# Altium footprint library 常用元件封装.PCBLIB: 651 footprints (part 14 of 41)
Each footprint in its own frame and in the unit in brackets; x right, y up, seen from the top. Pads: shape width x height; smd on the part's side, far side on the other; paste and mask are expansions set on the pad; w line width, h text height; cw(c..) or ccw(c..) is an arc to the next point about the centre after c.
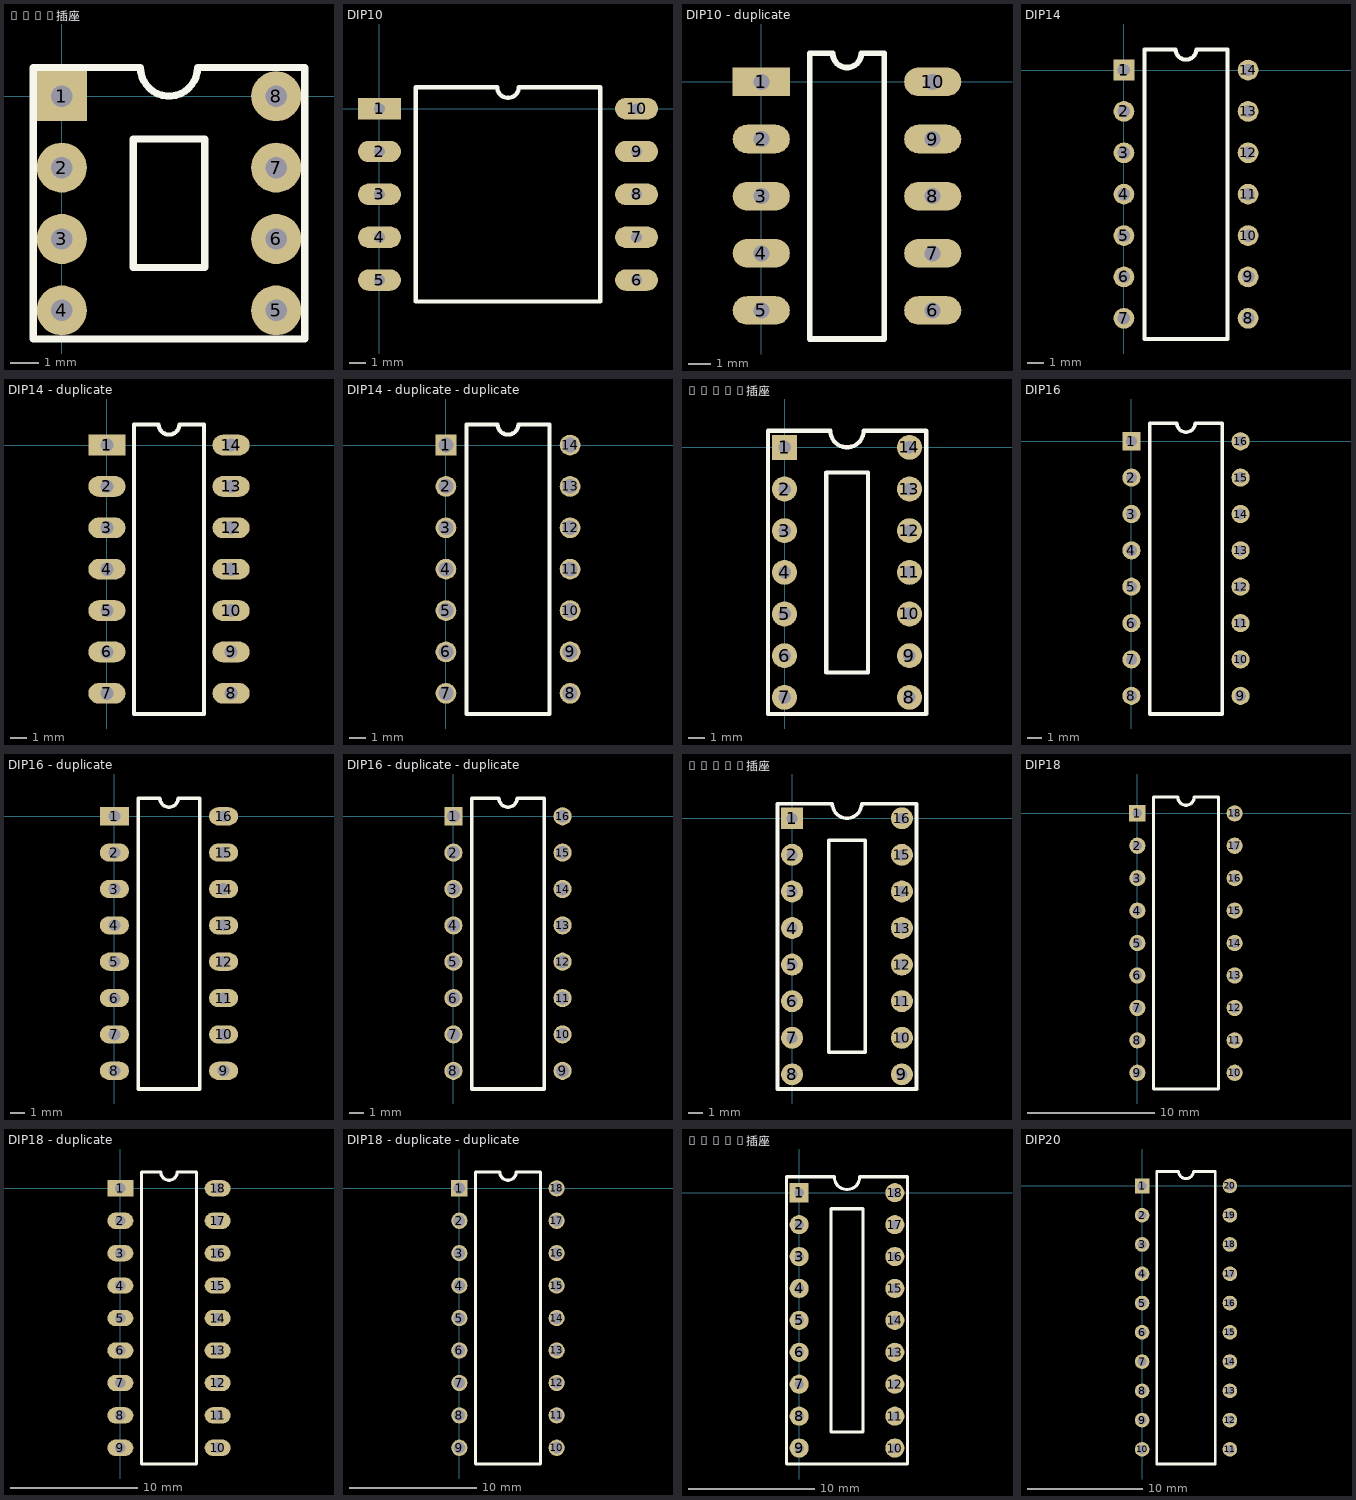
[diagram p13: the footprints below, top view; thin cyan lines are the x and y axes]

## DIP8插座 [mil]
pads (8):
  rect 70x70 hole 30: 1(0,0)
  round 70 hole 30: 2(0,-100) 3(0,-200) 4(0,-300) 5(300,-300) 6(300,-200) 7(300,-100) 8(300,0)
TopOverlay:
  lines w10: -40,-340 340,-340 340,40 190,40 cw(c150,40) 110,40 -40,40 -40,-340 ; 100,-240 100,-60 200,-60 200,-240 100,-240

## DIP10 [mil]
pads (10):
  rect 100x50 hole 25: 1(0,0)
  oval 100x50 hole 25: 2(0,-100) 3(0,-200) 4(0,-300) 5(0,-400) 6(600,-400) 7(600,-300) 8(600,-200) 9(600,-100) 10(600,0)
TopOverlay:
  lines w10: 85,-450 85,50 275,50 ccw(c300,50) 325,50 515,50 515,-450 85,-450

## DIP10 - duplicate [mil]
pads (10):
  rect 100x50 hole 28: 1(0,0)
  oval 100x50 hole 28: 2(0,-100) 3(0,-200) 4(0,-300) 5(0,-400) 6(300,-400) 7(300,-300) 8(300,-200) 9(300,-100) 10(300,0)
TopOverlay:
  lines w10: 85,-450 215,-450 215,50 175,50 cw(c150,50) 125,50 85,50 85,-450

## DIP14 [mil]
pads (14):
  rect 50x50 hole 30: 1(0,0)
  round 50 hole 30: 2(0,-100) 3(0,-200) 4(0,-300) 5(0,-400) 6(0,-500) 7(0,-600) 8(300,-600) 9(300,-500) 10(300,-400) 11(300,-300) 12(300,-200) 13(300,-100) 14(300,0)
TopOverlay:
  lines w10: 50,-650 50,50 125,50 ccw(c150,50) 175,50 250,50 250,-650 50,-650

## DIP14 - duplicate [mil]
pads (14):
  rect 90x50 hole 32: 1(0,0)
  oval 90x50 hole 32: 2(0,-100) 3(0,-200) 4(0,-300) 5(0,-400) 6(0,-500) 7(0,-600) 8(300,-600) 9(300,-500) 10(300,-400) 11(300,-300) 12(300,-200) 13(300,-100) 14(300,0)
TopOverlay:
  lines w10: 65,-650 65,50 125,50 ccw(c150,50) 175,50 235,50 235,-650 65,-650

## DIP14 - duplicate - duplicate [mm]
pads (14):
  rect 1.27x1.27 hole 0.9: 1(0,0)
  round 1.27 hole 0.9: 2(0,-2.54) 3(0,-5.08) 4(0,-7.62) 5(0,-10.16) 6(0,-12.7) 7(0,-15.24) 8(7.62,-15.24) 9(7.62,-12.7) 10(7.62,-10.16) 11(7.62,-7.62) 12(7.62,-5.08) 13(7.62,-2.54) 14(7.62,0)
TopOverlay:
  lines w0.254: 1.27,-16.51 6.35,-16.51 6.35,1.27 4.445,1.27 cw(c3.81,1.27) 3.175,1.27 1.27,1.27 1.27,-16.51

## DIP14插座 [mil]
pads (14):
  rect 60x60 hole 30: 1(0,0)
  round 60 hole 30: 2(0,-100) 3(0,-200) 4(0,-300) 5(0,-400) 6(0,-500) 7(0,-600) 8(300,-600) 9(300,-500) 10(300,-400) 11(300,-300) 12(300,-200) 13(300,-100) 14(300,0)
TopOverlay:
  lines w10: -40,-640 340,-640 340,40 190,40 cw(c150,40) 110,40 -40,40 -40,-640 ; 100,-540 100,-60 200,-60 200,-540 100,-540

## DIP16 [mil]
pads (16):
  rect 50x50 hole 30: 1(0,0)
  round 50 hole 30: 2(0,-100) 3(0,-200) 4(0,-300) 5(0,-400) 6(0,-500) 7(0,-600) 8(0,-700) 9(300,-700) 10(300,-600) 11(300,-500) 12(300,-400) 13(300,-300) 14(300,-200) 15(300,-100) 16(300,0)
TopOverlay:
  lines w10: 50,-750 250,-750 250,50 175,50 cw(c150,50) 125,50 50,50 50,-750

## DIP16 - duplicate [mil]
pads (16):
  rect 80x50 hole 32: 1(0,0)
  oval 80x50 hole 32: 2(0,-100) 3(0,-200) 4(0,-300) 5(0,-400) 6(0,-500) 7(0,-600) 8(0,-700) 9(300,-700) 10(300,-600) 11(300,-500) 12(300,-400) 13(300,-300) 14(300,-200) 15(300,-100) 16(300,0)
TopOverlay:
  lines w10: 65,-750 65,50 125,50 ccw(c150,50) 175,50 235,50 235,-750 65,-750

## DIP16 - duplicate - duplicate [mm]
pads (16):
  rect 1.27x1.27 hole 0.9: 1(0,0)
  round 1.27 hole 0.9: 2(0,-2.54) 3(0,-5.08) 4(0,-7.62) 5(0,-10.16) 6(0,-12.7) 7(0,-15.24) 8(0,-17.78) 9(7.62,-17.78) 10(7.62,-15.24) 11(7.62,-12.7) 12(7.62,-10.16) 13(7.62,-7.62) 14(7.62,-5.08) 15(7.62,-2.54) 16(7.62,0)
TopOverlay:
  lines w0.254: 1.27,-19.05 6.35,-19.05 6.35,1.27 4.445,1.27 cw(c3.81,1.27) 3.175,1.27 1.27,1.27 1.27,-19.05

## DIP16插座 [mil]
pads (16):
  rect 60x60 hole 30: 1(0,0)
  round 60 hole 30: 2(0,-100) 3(0,-200) 4(0,-300) 5(0,-400) 6(0,-500) 7(0,-600) 8(0,-700) 9(300,-700) 10(300,-600) 11(300,-500) 12(300,-400) 13(300,-300) 14(300,-200) 15(300,-100) 16(300,0)
TopOverlay:
  lines w10: -40,-740 340,-740 340,40 190,40 cw(c150,40) 110,40 -40,40 -40,-740 ; 100,-640 100,-60 200,-60 200,-640 100,-640

## DIP18 [mil]
pads (18):
  rect 50x50 hole 30: 1(0,0)
  round 50 hole 30: 2(0,-100) 3(0,-200) 4(0,-300) 5(0,-400) 6(0,-500) 7(0,-600) 8(0,-700) 9(0,-800) 10(300,-800) 11(300,-700) 12(300,-600) 13(300,-500) 14(300,-400) 15(300,-300) 16(300,-200) 17(300,-100) 18(300,0)
TopOverlay:
  lines w10: 50,-850 250,-850 250,50 175,50 cw(c150,50) 125,50 50,50 50,-850

## DIP18 - duplicate [mil]
pads (18):
  rect 80x50 hole 32: 1(0,0)
  oval 80x50 hole 32: 2(0,-100) 3(0,-200) 4(0,-300) 5(0,-400) 6(0,-500) 7(0,-600) 8(0,-700) 9(0,-800) 10(300,-800) 11(300,-700) 12(300,-600) 13(300,-500) 14(300,-400) 15(300,-300) 16(300,-200) 17(300,-100) 18(300,0)
TopOverlay:
  lines w10: 65,-850 235,-850 235,50 175,50 cw(c150,50) 125,50 65,50 65,-850

## DIP18 - duplicate - duplicate [mm]
pads (18):
  rect 1.27x1.27 hole 0.9: 1(0,0)
  round 1.27 hole 0.9: 2(0,-2.54) 3(0,-5.08) 4(0,-7.62) 5(0,-10.16) 6(0,-12.7) 7(0,-15.24) 8(0,-17.78) 9(0,-20.32) 10(7.62,-20.32) 11(7.62,-17.78) 12(7.62,-15.24) 13(7.62,-12.7) 14(7.62,-10.16) 15(7.62,-7.62) 16(7.62,-5.08) 17(7.62,-2.54) 18(7.62,0)
TopOverlay:
  lines w0.254: 1.27,-21.59 1.27,1.27 3.175,1.27 ccw(c3.81,1.27) 4.445,1.27 6.35,1.27 6.35,-21.59 1.27,-21.59

## DIP18插座 [mil]
pads (18):
  rect 60x60 hole 30: 1(0,0)
  round 60 hole 30: 2(0,-100) 3(0,-200) 4(0,-300) 5(0,-400) 6(0,-500) 7(0,-600) 8(0,-700) 9(0,-800) 10(300,-800) 11(300,-700) 12(300,-600) 13(300,-500) 14(300,-400) 15(300,-300) 16(300,-200) 17(300,-100) 18(300,0)
TopOverlay:
  lines w10: -40,-850 340,-850 340,50 190,50 cw(c150,50) 110,50 -40,50 -40,-850 ; 100,-750 200,-750 200,-50 100,-50 100,-750

## DIP20 [mil]
pads (20):
  rect 50x50 hole 30: 1(0,0)
  round 50 hole 30: 2(0,-100) 3(0,-200) 4(0,-300) 5(0,-400) 6(0,-500) 7(0,-600) 8(0,-700) 9(0,-800) 10(0,-900) 11(300,-900) 12(300,-800) 13(300,-700) 14(300,-600) 15(300,-500) 16(300,-400) 17(300,-300) 18(300,-200) 19(300,-100) 20(300,0)
TopOverlay:
  lines w10: 50,-950 250,-950 250,50 175,50 cw(c150,50) 125,50 50,50 50,-950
